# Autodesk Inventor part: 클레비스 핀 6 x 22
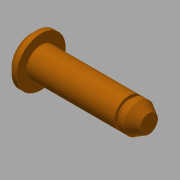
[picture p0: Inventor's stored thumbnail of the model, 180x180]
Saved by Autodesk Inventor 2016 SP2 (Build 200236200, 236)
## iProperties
IsCustomPart: 1
Created: 2017-08
Part Number: 클레비스 핀 6 x 22
Material: 강철
Description: 머리가 있는 클레비스 핀
Document SubType Name: Modeling
Standard: ISO 2341
Designer: mduedu
Standard Revision: Second edition 1986-11-01
Standards Organization: ISO
Language: ko-KR
Size Designation: B - 6 x 24
Categories: <MemberInstance><Categories><Category DisplayName="조임쇠" InternalName="e4da775c-781d-43d5-af7c-5136215cf5a6" Mnemonic="FSTN"><Category DisplayName="핀" InternalNa
Density: 7.85 g/cm^3
Appearance: 주황색
Author: mduedu
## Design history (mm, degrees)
sketch "스케치1"
  geometry: L1 (-2, 0)-(-2, 5); L2 (-2, 5)-(0, 5); L3 (0, 5)-(0, 3); L4 (0, 3)-(22, 3); L5 (22, 3)-(22, 0); L6 (-2, 0)-(22, 0); L7 (-7, 0)-(28, 0) reference; L8 (0, -1.96)-(0, 6.16) reference; C1 r 0.8 at (18.8, 0)
  constraints: 12 end point, 3 parallel, 2 collinear, 2 perpendicular, 1 centre point, 1 point on line, 1 vertical
  dimensions: "d0" = 6 diameter of L4 L6 (= NND); "d1" = 10 diameter of L2 L6 (= KOD); "d2" = 2 distance of L1.end L2.end (= KOH); "d3" = 22 distance of L3.end L4.end (= NLG); "d5" = 3.2 distance from line of L5 C1.centre (= DIST); "d6" = 1.6 diameter of C1 (= BOR)
revolve "본체" stored, may be unused: angle "d4" = 90 deg
workplane "Work Plane1"
node "작업 평면4"
sketch "스케치2"
  geometry: C1 r 3 at (0, 0) reference; C2 r 2.425 at (0, 0); 1 further point
  constraints: 1 centre point, 1 coincident
  dimensions: "d33" = 4.85 diameter of C2
extrude "돌출2" cut sketch "스케치2" distance "d34" = 0.7; taper "d35" = 0 deg
body "Solid1"
chamfer "모따기1" distance "d9" = 1 (= PHH2); stored, may be unused: angle "d10" = 45 deg (= FAWI2), second distance "d16" = 1 (= PHH2)
chamfer "모따기2" distance "d11" = 2 (= PHH1); stored, may be unused: angle "d12" = 30 deg (= FAWI1), second distance "d17" = 2 (= PHH1)
other parameters: "PHH1" = 2 [user parameter; used in 2 equation terms], "PHH2" = 1 [user parameter; used in 2 equation terms], "KOD" = 10 [user parameter; used in 1 equation term], "KOH" = 2 [user parameter; used in 1 equation term], "NND" = 6 [user parameter; used in 1 equation term], "FAWI1" = 30 deg [user parameter; used in 1 equation term], "FAWI2" = 45 deg [user parameter; used in 1 equation term], "DIST" = 3.2 [user parameter; used in 1 equation term], "BOR" = 1.6 [user parameter; used in 1 equation term], "NLG" = 22 [user parameter; used in 1 equation term], "d13" = 0, "d14" = 0, "d30" = 0, "d32" = 18
